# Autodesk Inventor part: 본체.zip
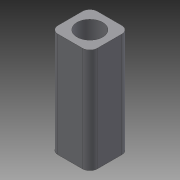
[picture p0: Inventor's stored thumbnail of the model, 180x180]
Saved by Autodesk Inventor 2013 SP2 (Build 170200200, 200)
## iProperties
Created: 2024-07
Part Number: 본체.zip
Material: Generic
Document SubType Name: Modeling
Designer: a
Density: 1 g/cm^3
Author: a
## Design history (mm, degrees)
sketch "스케치1"
  geometry: L1 (-25, 40)-(25, 40); L2 (40, 25)-(40, -25); L3 (25, -40)-(-25, -40); L4 (-40, -25)-(-40, 25); L5 (-40, 40)-(40, -40); L6 (40, 40)-(-40, -40); A1 r 15 centre (-25, 25) between (-25, 40) and (-40, 25); A2 r 15 centre (25, 25) between (40, 25) and (25, 40); A3 r 15 centre (-25, -25) between (-40, -25) and (-25, -40); A4 r 15 centre (25, -25) between (25, -40) and (40, -25); 1 further point
  constraints: 12 end point, 8 point on circle, 8 point on line, 8 tangent, 4 centre point, 3 equal radius, 2 midpoint, 2 parallel, 1 horizontal, 1 perpendicular
  dimensions: "d0" = 80 distance of L5.start L6.start; "d2" = 80 distance of L6.start L5.end; "d3" = 15 radius of A1
extrude "돌출1" new body sketch "스케치1" stored distance "d4" = 212; taper "d5" = 0 deg
sketch "스케치2"
  geometry: L1 (0, 212)-(50, 212) reference; 2 further points
  constraints: 1 vertical alignment, 1 other
  dimensions: "d6" = 90 distance from line of L1 point (25, 122)
feature "엠보싱1" sketch "스케치2" dims "d7" = 0.5, "d8" = 0
sketch "스케치3"
  geometry: C1 r 20.5 at (0, 0); 1 further point
  constraints: 1 centre point, 1 coincident
  dimensions: "d9" = 41 diameter of C1
extrude "돌출2" cut sketch "스케치3" distance "d11" = 2; taper "d12" = 0 deg
sketch "스케치4"
  geometry: C1 r 32 at (0, 0); 5 further points
  constraints: 1 centre point, 1 coincident, 1 vertical alignment, 5 other
  dimensions: "d13" = 64 diameter of C1; "d15" = 31.5 distance of point (0, 0) point (0, 31.5); "d18" = 360 deg dimension on C1.centre point (0, 31.5) (derived)
hole "구멍1" sketch "스케치4" at (0, 31.5), (-31.5, 0), (0, -31.5), (31.5, 0) diameter "d20" = 3.242; stored, may be unused: countersink angle "d24" = 82 deg, drill point angle "d26" = 118 deg; dims "d21" = 12, "d22" = 3.023, "d23" = 2, "d25" = 14
sketch "스케치5"
  geometry: C1 r 26 at (0, 0); 1 further point
  constraints: 1 centre point, 1 coincident
  dimensions: "d27" = 52 diameter of C1
extrude "돌출3" cut sketch "스케치5" distance "d29" = 217; taper "d30" = 0 deg
node "솔리드1"
